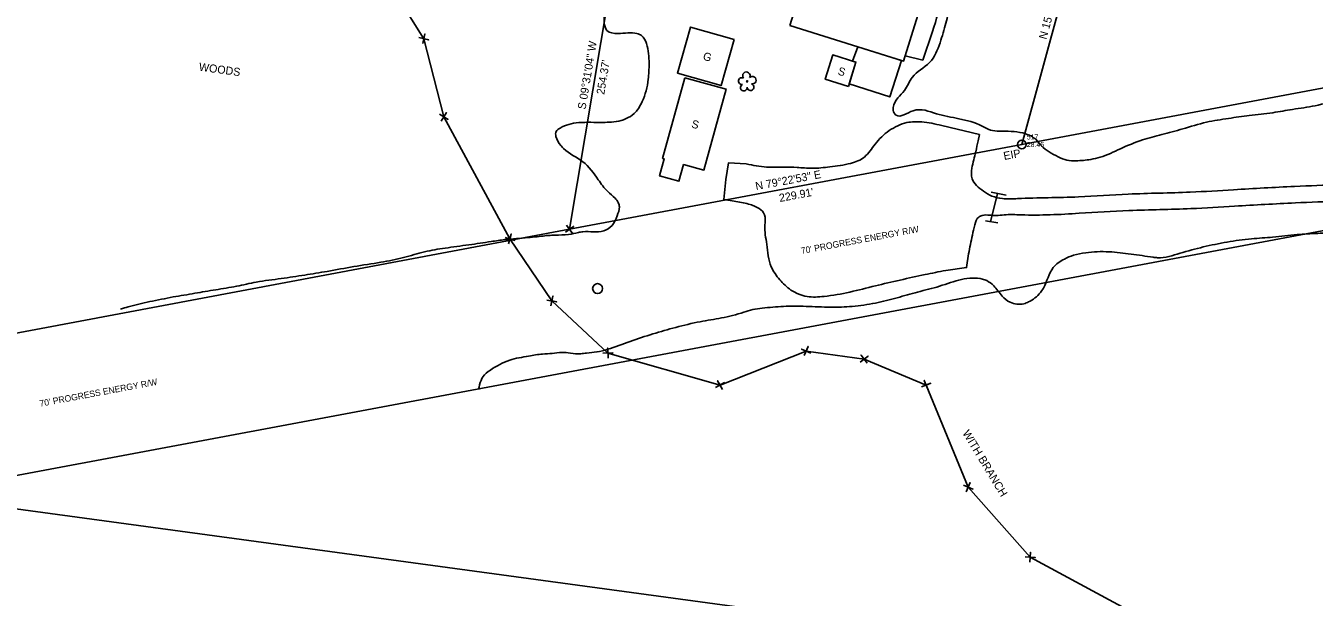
# Model space of a CAD drawing. Extents: x 2627243 to 2636458, y 566398 to 571062.
# Drawn here: x 2634753 to 2635397, y 568538 to 568823 of the extents above; entities that cross this region are included whole.
import ezdxf

# ---------------------------------------------------------------- set-up
doc = ezdxf.new("R2010")
doc.units = 0
for name, color, linetype in [('Exist Building', 7, 'Continuous'), ('Exist Building Deck Patio', 7, 'Continuous'), ('Exist Building Text', 7, 'Continuous'), ('Exist Property Corner CELL', 7, 'Continuous'), ('Exist Property Iron Pin CELL', 7, 'Continuous'), ('Exist Property Iron Pin Cogo Elevation', 7, 'Continuous'), ('Exist Property Iron Pin Cogo Number', 7, 'Continuous'), ('Exist Property Iron Pin Text', 7, 'Continuous'), ('Exist Property Line', 7, 'Continuous'), ('Exist Property Line Text', 7, 'Continuous'), ('Exist Right of Way Easement Line', 7, 'Continuous'), ('Exist Right of Way Line Text', 7, 'Continuous'), ('Exist Roads EOP Other', 7, 'Continuous'), ('Exist Roads Soil', 7, 'Continuous'), ('Exist Structure Major Bridge WW', 7, 'Continuous'), ('Exist Structure Minor Culvert Topo', 7, 'Continuous'), ('Exist Utilities Other Pole CELL', 7, 'Continuous'), ('Exist Vegetation Tree CELL', 7, 'Continuous'), ('Exist Vegetation Woods Line', 7, 'Continuous'), ('Exist Vegetation Woods Line Text', 7, 'Continuous'), ('Scratch_Level_2', 7, 'Continuous')]:
    doc.layers.add(name, color=color, linetype=linetype)

# ---------------------------------------------------------------- blocks, each defined once
blk = doc.blocks.new('EXIST PROPERTY IRON PIN')
at = {"layer": 'Exist Property Iron Pin CELL'}
for radius in [0.0441, 0.00141]:
    blk.add_circle((0, 0), radius, dxfattribs=at)
blk = doc.blocks.new('EXIST VEGETATION TREE')
at = {"layer": 'Exist Vegetation Tree CELL'}
blk.add_line((0, 0), (0, 0), dxfattribs=at)
blk.add_circle((0, 0), 0.00652, dxfattribs=at)
for centre, radius, start, end in [((-0.052, 0.003), 0.0345, 62.6636, 279.3457), ((-0.008, 0.057), 0.0371, 330.1651, 219.7134), ((0.051, 0.012), 0.038, 257.1011, 134.1999), ((-0.034, -0.062), 0.0338, 111.5671, 6.231), ((0.033, -0.058), 0.034, 181.2822, 74.56)]:
    blk.add_arc(centre, radius, start, end, dxfattribs=at)
blk = doc.blocks.new('EXIST UTILITIES OTHER POLE')
at = {"layer": 'Exist Utilities Other Pole CELL'}
blk.add_circle((0, 0), 0.0493, dxfattribs=at)

msp = doc.modelspace()

# ---------------------------------------------------------------- linework, layer by layer
at = {"layer": 'Exist Building'}
for points in [[(2635134.83, 568823.61), (2635191.68, 568805.87), (2635202.04, 568839.07), (2635145.19, 568856.81), (2635134.83, 568823.61)], [(2635107.06, 568816.58), (2635100.52, 568793.6), (2635078.68, 568799.81), (2635085.21, 568822.8), (2635107.06, 568816.58)], [(2635164.13, 568793.17), (2635152.59, 568796.74), (2635156.36, 568808.92), (2635167.9, 568805.35), (2635164.13, 568793.17)], [(2635082.39, 568797.54), (2635071.34, 568757.25), (2635072.16, 568757.03), (2635069.82, 568748.49), (2635079.46, 568745.85), (2635081.75, 568754.17), (2635091.93, 568751.37), (2635103.05, 568791.87), (2635082.39, 568797.54)]]:
    msp.add_lwpolyline(points, dxfattribs=at)
at = {"layer": 'Exist Building Deck Patio'}
msp.add_lwpolyline([(2635190.72, 568806.17), (2635168.92, 568812.97), (2635166.27, 568805.85), (2635167.9, 568805.35), (2635164.53, 568794.47), (2635184.78, 568787.94), (2635190.72, 568806.17)], dxfattribs=at)
at = {"layer": 'Exist Property Corner CELL'}
for p, q in [((2634952, 568817), (2634952, 568817)), ((2634962, 568778), (2634962, 568778)), ((2635024.8, 568721.82), (2635024.8, 568721.82)), ((2634995, 568717), (2634995, 568717)), ((2635016, 568686), (2635016, 568686)), ((2635044, 568660), (2635044, 568660)), ((2635143, 568661), (2635143, 568661)), ((2635172, 568657), (2635172, 568657)), ((2635100, 568644), (2635100, 568644)), ((2635203, 568644), (2635203, 568644)), ((2635224, 568593), (2635224, 568593)), ((2635255, 568558), (2635255, 568558))]:
    msp.add_line(p, q, dxfattribs=at)
for points in [[(2634949.56, 568817.56), (2634954.44, 568816.44), (2634952, 568817), (2634952.56, 568819.44), (2634951.44, 568814.56)], [(2634959.85, 568779.27), (2634964.15, 568776.73), (2634962, 568778), (2634963.27, 568780.15), (2634960.73, 568775.85)], [(2635023.35, 568723.86), (2635026.25, 568719.79), (2635024.8, 568721.82), (2635026.84, 568723.27), (2635022.76, 568720.37)], [(2634992.6, 568717.71), (2634997.4, 568716.29), (2634995, 568717), (2634995.71, 568719.4), (2634994.29, 568714.6)], [(2635013.54, 568686.47), (2635018.46, 568685.53), (2635016, 568686), (2635016.47, 568688.46), (2635015.53, 568683.54)], [(2635142.01, 568658.71), (2635143.99, 568663.29), (2635143, 568661), (2635140.71, 568661.99), (2635145.29, 568660.01)], [(2635041.5, 568659.91), (2635046.5, 568660.09), (2635044, 568660), (2635043.91, 568662.5), (2635044.09, 568657.5)], [(2635170.01, 568655.49), (2635173.99, 568658.51), (2635172, 568657), (2635170.49, 568658.99), (2635173.51, 568655.01)], [(2635097.81, 568642.79), (2635102.19, 568645.21), (2635100, 568644), (2635098.79, 568646.19), (2635101.21, 568641.81)], [(2635200.69, 568643.05), (2635205.31, 568644.95), (2635203, 568644), (2635202.05, 568646.31), (2635203.95, 568641.69)], [(2635221.69, 568593.96), (2635226.31, 568592.04), (2635224, 568593), (2635224.96, 568595.31), (2635223.04, 568590.69)], [(2635252.5, 568558.15), (2635257.5, 568557.85), (2635255, 568558), (2635255.15, 568560.5), (2635254.85, 568555.5)]]:
    msp.add_lwpolyline(points, dxfattribs=at)
at = {"layer": 'Exist Property Line'}
for p, q in [((2635066.86, 568972.7), (2635024.8, 568721.82)), ((2635250.77, 568764.19), (2635289.21, 568904.37)), ((2634927, 568857), (2634952, 568817)), ((2634952, 568817), (2634962, 568778)), ((2634962, 568778), (2634995, 568717)), ((2635024.8, 568721.82), (2635250.77, 568764.19)), ((2634995, 568717), (2635016, 568686)), ((2635016, 568686), (2635044, 568660)), ((2635044, 568660), (2635100, 568644)), ((2635100, 568644), (2635143, 568661)), ((2635143, 568661), (2635172, 568657)), ((2635172, 568657), (2635203, 568644)), ((2635203, 568644), (2635224, 568593)), ((2635224, 568593), (2635255, 568558)), ((2635255, 568558), (2635305, 568531))]:
    msp.add_line(p, q, dxfattribs=at)
at = {"layer": 'Exist Right of Way Easement Line'}
for p, q in [((2635250.77, 568764.19), (2635557.9, 568821.77)), ((2634448.9, 568542.63), (2635701.81, 568777.53)), ((2634437.06, 568611.63), (2635024.8, 568721.82))]:
    msp.add_line(p, q, dxfattribs=at)
at = {"layer": 'Exist Roads EOP Other'}
msp.add_lwpolyline([(2635192.52, 568808.53), (2635201.28, 568806.38), (2635206.22, 568820.58)], dxfattribs=at)
msp.add_spline([(2635206.22, 568820.58), (2635211.23, 568838.64), (2635213.65, 568852.93), (2635214.79, 568872.07), (2635215.18, 568880.35), (2635224.83, 568910.47), (2635232.7, 568934.34), (2635239, 568953.3), (2635241.72, 568959.88)], degree=3, dxfattribs=at)
at = {"layer": 'Exist Roads Soil'}
for points in [[(2635228.96, 568765.97), (2635229.56, 568769.13), (2635210.76, 568773.67)], [(2635113.11, 568754.48), (2635104.3, 568755.06), (2635102.86, 568746.64), (2635101.95, 568736.7), (2635107.02, 568735.84)], [(2635212.77, 568701.28), (2635223.19, 568702.73), (2635224.2, 568709.54)]]:
    msp.add_lwpolyline(points, dxfattribs=at)
for points in [[(2635571.91, 568859.64), (2635576.62, 568853.76), (2635578.9, 568849.62), (2635580.1, 568846.87), (2635581.4, 568842.64), (2635582.03, 568835.31), (2635579.67, 568826.8), (2635576.79, 568818.12), (2635573.37, 568808.95), (2635568.81, 568799.69), (2635558.82, 568781.82), (2635550.51, 568768.25), (2635542.01, 568761.32), (2635530.56, 568754.08), (2635519.64, 568750.07), (2635505.07, 568748.01), (2635485.97, 568747.3), (2635462.75, 568746.91), (2635439.88, 568746.4), (2635409.45, 568744.24), (2635387.04, 568743.22), (2635356.63, 568741.56), (2635334.95, 568740.38), (2635303.95, 568739.37), (2635279.14, 568738.01), (2635248.7, 568737.15), (2635241.06, 568737.16), (2635235.84, 568738.43), (2635231.69, 568740.79), (2635228.12, 568743.71), (2635225.91, 568747.07), (2635225.85, 568752.29), (2635227.78, 568760.6), (2635228.96, 568765.97)], [(2635224.2, 568709.54), (2635226.06, 568718.94), (2635227.3, 568724.04), (2635229.29, 568727.96), (2635230.99, 568728.71), (2635234.78, 568728.91), (2635238.09, 568728.71), (2635241.91, 568729.04), (2635250.47, 568729.02), (2635279.5, 568729.8), (2635304.31, 568731.16), (2635335.31, 568732.16), (2635357.08, 568733.35), (2635387.45, 568735.01), (2635409.93, 568736.03), (2635440.26, 568738.19), (2635462.91, 568738.69), (2635486.19, 568739.08), (2635505.8, 568739.82), (2635521.66, 568742.05), (2635534.22, 568746.67), (2635546.82, 568754.64), (2635556.79, 568762.76), (2635565.91, 568777.66), (2635576.09, 568795.87), (2635580.92, 568805.69), (2635584.54, 568815.38), (2635587.54, 568824.41), (2635590.04, 568830.98), (2635592.12, 568836.02), (2635594.53, 568838.76), (2635597.52, 568842.07), (2635602.81, 568846.3), (2635609.11, 568848.26)], [(2635210.76, 568773.67), (2635200.77, 568775.47), (2635193.39, 568775.09), (2635184.53, 568771.11), (2635177.52, 568764.37), (2635172.15, 568757.93), (2635165.27, 568754.77), (2635154.83, 568753), (2635145.98, 568752.32), (2635138.52, 568752.72), (2635131.64, 568752.85), (2635123.27, 568752.88), (2635113.11, 568754.48)], [(2635107.02, 568735.84), (2635114.3, 568734.41), (2635119.49, 568732.19), (2635122.26, 568729.08), (2635122.4, 568723.91), (2635123.34, 568714.3), (2635125.62, 568703.06), (2635129.84, 568696.62), (2635135.43, 568691.46), (2635143.51, 568688.26), (2635151.95, 568688.27), (2635177.6, 568693.56), (2635202.44, 568699.16), (2635212.77, 568701.28)]]:
    msp.add_spline(points, degree=3, dxfattribs=at)
at = {"layer": 'Exist Structure Major Bridge WW'}
for p, q in [((2635242.89, 568738.82), (2635235.44, 568740.35)), ((2635232.56, 568725.99), (2635238.86, 568724.97))]:
    msp.add_line(p, q, dxfattribs=at)
at = {"layer": 'Exist Structure Minor Culvert Topo'}
msp.add_lwpolyline([(2635238.65, 568739.69), (2635235.09, 568725.58)], dxfattribs=at)
at = {"layer": 'Exist Vegetation Woods Line'}
for points in [[(2634648.6, 568711.49), (2634653.17, 568721.16), (2634653.75, 568723.17), (2634653.06, 568734.66), (2634652.68, 568736.88), (2634653.81, 568745.82), (2634654.68, 568748.01), (2634657.46, 568751.42), (2634662.01, 568762.1), (2634666.13, 568771.5), (2634670.48, 568781.85), (2634675.66, 568793.14), (2634680.22, 568804.46), (2634684.29, 568815.25), (2634687.61, 568827.22), (2634691.5, 568836.67), (2634694.84, 568847.62), (2634698.7, 568859.72), (2634702.61, 568870.42), (2634706.55, 568881.75), (2634708.6, 568893.12), (2634707.86, 568904.36), (2634707.86, 568914.43), (2634708.96, 568924.38), (2634711.31, 568935.94), (2634713.66, 568947.5), (2634714.72, 568959.47), (2634715.61, 568970.72), (2634714.71, 568981.25), (2634713.31, 568991.26), (2634709.85, 569001.6), (2634703.68, 569011.68), (2634697.55, 569021.37), (2634694.65, 569026.93), (2634691.13, 569037.04), (2634687.16, 569048.5), (2634684.14, 569055.22), (2634683.99, 569062.94), (2634686.08, 569063.85), (2634688.25, 569063.99), (2634698.88, 569060.85), (2634708.91, 569057.33), (2634719, 569054.05), (2634729, 569050.93), (2634740.66, 569049.06), (2634752.01, 569048.01), (2634763.88, 569046.48), (2634774.81, 569046.41), (2634786.68, 569047.14), (2634798.51, 569045.99), (2634811.39, 569044.48), (2634822.06, 569043.21), (2634833.27, 569042.7), (2634842.82, 569040.93), (2634849.22, 569038.61), (2634860.81, 569037.52), (2634873.07, 569036.65), (2634877.7, 569036.49), (2634881.96, 569037.54), (2634884.26, 569038.05)], [(2634884.26, 569038.05), (2634886.56, 569037.01), (2634891.39, 569036.52), (2634901.12, 569034.15), (2634915.14, 569029.5), (2634925.06, 569026.83), (2634935.25, 569023.71), (2634945.25, 569020.89), (2634956.29, 569018.71), (2634966.67, 569016.94), (2634978.64, 569014.93), (2634988.87, 569013.07), (2634993.11, 569012.22), (2635004.32, 569010.76), (2635009.25, 569010.13), (2635021.09, 569007.01), (2635032.91, 569003.26), (2635042.45, 568999.53), (2635053.53, 568995.31), (2635059.94, 568992.31), (2635063.96, 568988.84), (2635068.1, 568983.18), (2635069.84, 568978.09), (2635070.85, 568973.16), (2635071.01, 568962.34), (2635071.84, 568951.11), (2635071.39, 568945.89), (2635069.32, 568935.33), (2635067.26, 568929.72), (2635061.77, 568919.7), (2635060.58, 568917.31), (2635058.33, 568907.05), (2635057.25, 568901.84), (2635053.76, 568892.25), (2635052.34, 568887.25), (2635051.59, 568875.24), (2635053.09, 568865.26), (2635053.64, 568861.07), (2635052.91, 568856.29), (2635050.59, 568850.1), (2635045.24, 568840.18), (2635043.57, 568836.25), (2635042.27, 568830.08), (2635042.12, 568825.04), (2635043.5, 568821.17), (2635048.99, 568819.65), (2635058.5, 568819.6), (2635060.79, 568818.56), (2635063.29, 568814.56), (2635064.54, 568804.63), (2635064.11, 568796.74), (2635061.15, 568785.62), (2635058.65, 568781.38), (2635057.09, 568779.59), (2635053.09, 568777.09), (2635050.58, 568776.14), (2635045.71, 568775.37), (2635041.48, 568775.21), (2635029.4, 568775.09), (2635024.38, 568774.22), (2635020.15, 568772.41), (2635018.11, 568770.72), (2635018.04, 568768.2), (2635020.42, 568763.72), (2635021.83, 568762.12), (2635031.48, 568755.58), (2635039.16, 568746.57), (2635043.88, 568740.65), (2635047.57, 568737.39), (2635049.1, 568735.26), (2635049.71, 568732.96), (2635048.56, 568728.53), (2635046.04, 568723.66), (2635041.88, 568721.07), (2635031.49, 568720.56), (2635029.24, 568720.19), (2635024.31, 568719.18), (2635017.66, 568718.94), (2635010.8, 568718.37), (2635006.37, 568717.87), (2635004.04, 568717.65), (2634992.51, 568716.64), (2634985.69, 568715.69), (2634974.53, 568714.08), (2634962.6, 568712.4), (2634952.4, 568710.58), (2634941.84, 568707.7), (2634930.51, 568705.37), (2634917.06, 568703.16), (2634903.7, 568700.8), (2634892.48, 568698.95), (2634880.79, 568697.22), (2634868.31, 568695.41), (2634858.45, 568693.38), (2634848.02, 568691.61), (2634837.58, 568689.84), (2634826.76, 568688.03)], [(2635492.54, 568795.19), (2635479.16, 568793.02), (2635467.7, 568791.24), (2635456.67, 568790.74), (2635444.39, 568790.29), (2635432.32, 568789.15), (2635421.48, 568788.36), (2635410.18, 568786.67), (2635397.28, 568783.56), (2635386.06, 568781.72), (2635376.17, 568780.08), (2635364.43, 568778.73), (2635354.05, 568777.2), (2635343.08, 568775.3), (2635331.15, 568771.98), (2635320.73, 568769.19), (2635311.09, 568766.47), (2635300.04, 568762.05), (2635289.92, 568757.8), (2635285.23, 568756.73), (2635277.84, 568756.03), (2635273.33, 568756.31), (2635268.92, 568758.09), (2635260.55, 568763.58), (2635257.74, 568766.77), (2635255.55, 568768.29), (2635251.24, 568769.93), (2635239.52, 568770.86), (2635235.08, 568771.38), (2635230.96, 568773.35), (2635219.39, 568777.05), (2635208.16, 568779.52), (2635196.47, 568781.08), (2635187.96, 568778.87), (2635186.7, 568780.55), (2635186.57, 568782.74), (2635188.8, 568787.42), (2635192.21, 568791.2), (2635196, 568797.68), (2635204.71, 568805.18), (2635209.91, 568815.01), (2635212.83, 568824.87), (2635214.04, 568829.53), (2635215.88, 568834.18), (2635222.09, 568844.04), (2635223.91, 568848.05), (2635225.59, 568858.58), (2635225.93, 568863.32), (2635228.75, 568866.72), (2635240.33, 568866.33), (2635249.72, 568867.45), (2635259.28, 568861.05), (2635261.39, 568860.31), (2635266.38, 568859.92), (2635272.62, 568861.13), (2635277.15, 568863.13), (2635280.65, 568866.76), (2635282.47, 568870.78), (2635283.53, 568875.35), (2635284.28, 568885.71), (2635286.48, 568895.73), (2635287.85, 568897.82), (2635292.22, 568898.08), (2635298.32, 568897.56), (2635308.38, 568894.97), (2635321.22, 568891.24), (2635332.17, 568885.92), (2635342.65, 568881.33), (2635352.8, 568878.6), (2635362.53, 568876.22), (2635372.41, 568873.94), (2635384.16, 568872.61), (2635393.86, 568869.6), (2635403.4, 568865.87), (2635414, 568861.77), (2635423.73, 568857.74), (2635435.77, 568853.3), (2635447.77, 568849.26), (2635457.61, 568845.71), (2635468.84, 568841.59), (2635480.23, 568838.19), (2635490.61, 568834.77), (2635500.22, 568831.91), (2635510.19, 568829.48), (2635519.8, 568826.62), (2635530.53, 568823.63), (2635540.61, 568821.68), (2635545.65, 568819.87), (2635548.04, 568818.69), (2635551.48, 568815.48), (2635553.17, 568810.14), (2635553.2, 568808.1), (2635549.01, 568805.9), (2635543.93, 568804.8), (2635533.96, 568803.93), (2635521.42, 568802.9), (2635514.24, 568801.52)], [(2634979.32, 568641.8), (2634980.63, 568646.32), (2634981.55, 568648.14), (2634985.24, 568651.47), (2634994.9, 568656.46), (2635004.37, 568658.46), (2635011.34, 568659.51), (2635016.11, 568659.8), (2635020.92, 568660.33), (2635025.28, 568659.96), (2635030.41, 568659.66), (2635033.28, 568660.01), (2635038.49, 568660.58), (2635043.87, 568661.87), (2635055.05, 568665.76), (2635066.46, 568669.58), (2635077.86, 568672.78), (2635090.08, 568675.66), (2635100.66, 568677.52), (2635111.86, 568680.39), (2635116.36, 568681.75), (2635121.09, 568682.44), (2635131.69, 568683.28), (2635142.99, 568683.33), (2635155.2, 568682.91), (2635166.08, 568683.31), (2635177.63, 568684.95), (2635188.53, 568687.63), (2635198.7, 568690.47), (2635209.66, 568693.39), (2635220.72, 568696.79), (2635226.08, 568697.46), (2635231.16, 568696.92), (2635233.27, 568696.17), (2635236.73, 568693.59), (2635240.99, 568688.42), (2635244.97, 568685.34), (2635251.79, 568684.65), (2635254.15, 568685.5), (2635260.06, 568690.22), (2635261.58, 568692.41), (2635266.5, 568702.69), (2635272.07, 568706.98), (2635276.68, 568708.83), (2635282.69, 568710.1), (2635294.34, 568710.58), (2635305.37, 568709.42), (2635316.43, 568707.87), (2635318.65, 568707.61), (2635329.83, 568709.85), (2635341.47, 568712.99), (2635353.33, 568715.44), (2635365.51, 568717.06), (2635376.11, 568717.91), (2635388.32, 568719.14), (2635398.63, 568719.8), (2635408.69, 568720.51), (2635420.7, 568721.41), (2635434.38, 568722.94), (2635447.04, 568724.45), (2635460.18, 568725.85), (2635470.91, 568727.8), (2635484.33, 568730.41), (2635494.59, 568731.45), (2635507.71, 568732.22), (2635517.74, 568733.33), (2635522.08, 568733.97), (2635526.16, 568735.69), (2635537.96, 568737.91), (2635549.01, 568740.68), (2635559.21, 568744.15), (2635569.66, 568746.55), (2635580.06, 568747.06), (2635590.1, 568747.15), (2635600.63, 568747.12), (2635613.02, 568746.41), (2635623.03, 568746.88), (2635631.94, 568746.47), (2635635.95, 568748.48)], [(2634826.76, 568688.03), (2634815.05, 568685.67), (2634804.3, 568683.08), (2634800.48, 568681.94)]]:
    msp.add_spline(points, degree=3, dxfattribs=at)
at = {"layer": 'Scratch_Level_2'}
msp.add_lwpolyline([(2633945.71, 569750.8), (2635590.54, 569527.29), (2635449.16, 568486.85), (2633804.33, 568710.36)], close=True, dxfattribs=at)

# ---------------------------------------------------------------- block references
at = {"layer": 'Exist Property Iron Pin CELL', "xscale": 50, "yscale": 50}
msp.add_blockref('EXIST PROPERTY IRON PIN', (2635250.77, 568764.19), dxfattribs=at)
at = {"layer": 'Exist Utilities Other Pole CELL', "xscale": 50, "yscale": 50}
msp.add_blockref('EXIST UTILITIES OTHER POLE', (2635038.82, 568692.21), dxfattribs=at)
at = {"layer": 'Exist Vegetation Tree CELL', "xscale": 50, "yscale": 50}
msp.add_blockref('EXIST VEGETATION TREE', (2635113.57, 568795.71), dxfattribs=at)

# ---------------------------------------------------------------- texts
at = {"layer": 'Exist Building Text'}
for s, rotation, p in [('G', 344.12879, (2635091.16, 568806.63)), ('S', 342.79522, (2635158.51, 568799.22)), ('S', 344.65662, (2635085.41, 568772.75))]:
    msp.add_text(s, height=4, rotation=rotation, dxfattribs=at).set_placement(p)
at = {"layer": 'Exist Property Iron Pin Cogo Elevation'}
msp.add_text('28.46', height=2.5, dxfattribs=at).set_placement((2635253.27, 568762.94))
at = {"layer": 'Exist Property Iron Pin Cogo Number'}
msp.add_text('517', height=2.5, dxfattribs=at).set_placement((2635253.27, 568766.69))
at = {"layer": 'Exist Property Iron Pin Text'}
msp.add_text('EIP', height=4, rotation=10.61865, dxfattribs=at).set_placement((2635241.99, 568756.42))
at = {"layer": 'Exist Property Line Text'}
for s, rotation, p in [('N 15%%D20\'06" E', 74.66503, (2635263.02, 568816.42)), ('S 09%%D31\'04" W', 80.4821, (2635032.77, 568781.45)), ("254.37'", 80.4821, (2635042.13, 568788.88)), ('N 79%%D22\'53" E', 10.61865, (2635118.05, 568741.34)), ("229.91'", 10.61865, (2635129.91, 568735.43)), ('WITH BRANCH', 301.1593, (2635220.96, 568620.05))]:
    msp.add_text(s, height=4, rotation=rotation, dxfattribs=at).set_placement(p)
at = {"layer": 'Exist Right of Way Line Text'}
for p in [(2635140.73, 568709.43), (2634760.32, 568633.13)]:
    msp.add_text("70' PROGRESS ENERGY R/W", height=3.2, rotation=10.61865, dxfattribs=at).set_placement(p)
at = {"layer": 'Exist Vegetation Woods Line Text'}
msp.add_text('WOODS', height=4, rotation=352.32218, dxfattribs=at).set_placement((2634839.46, 568801.09))

doc.saveas('drawing.dxf')
